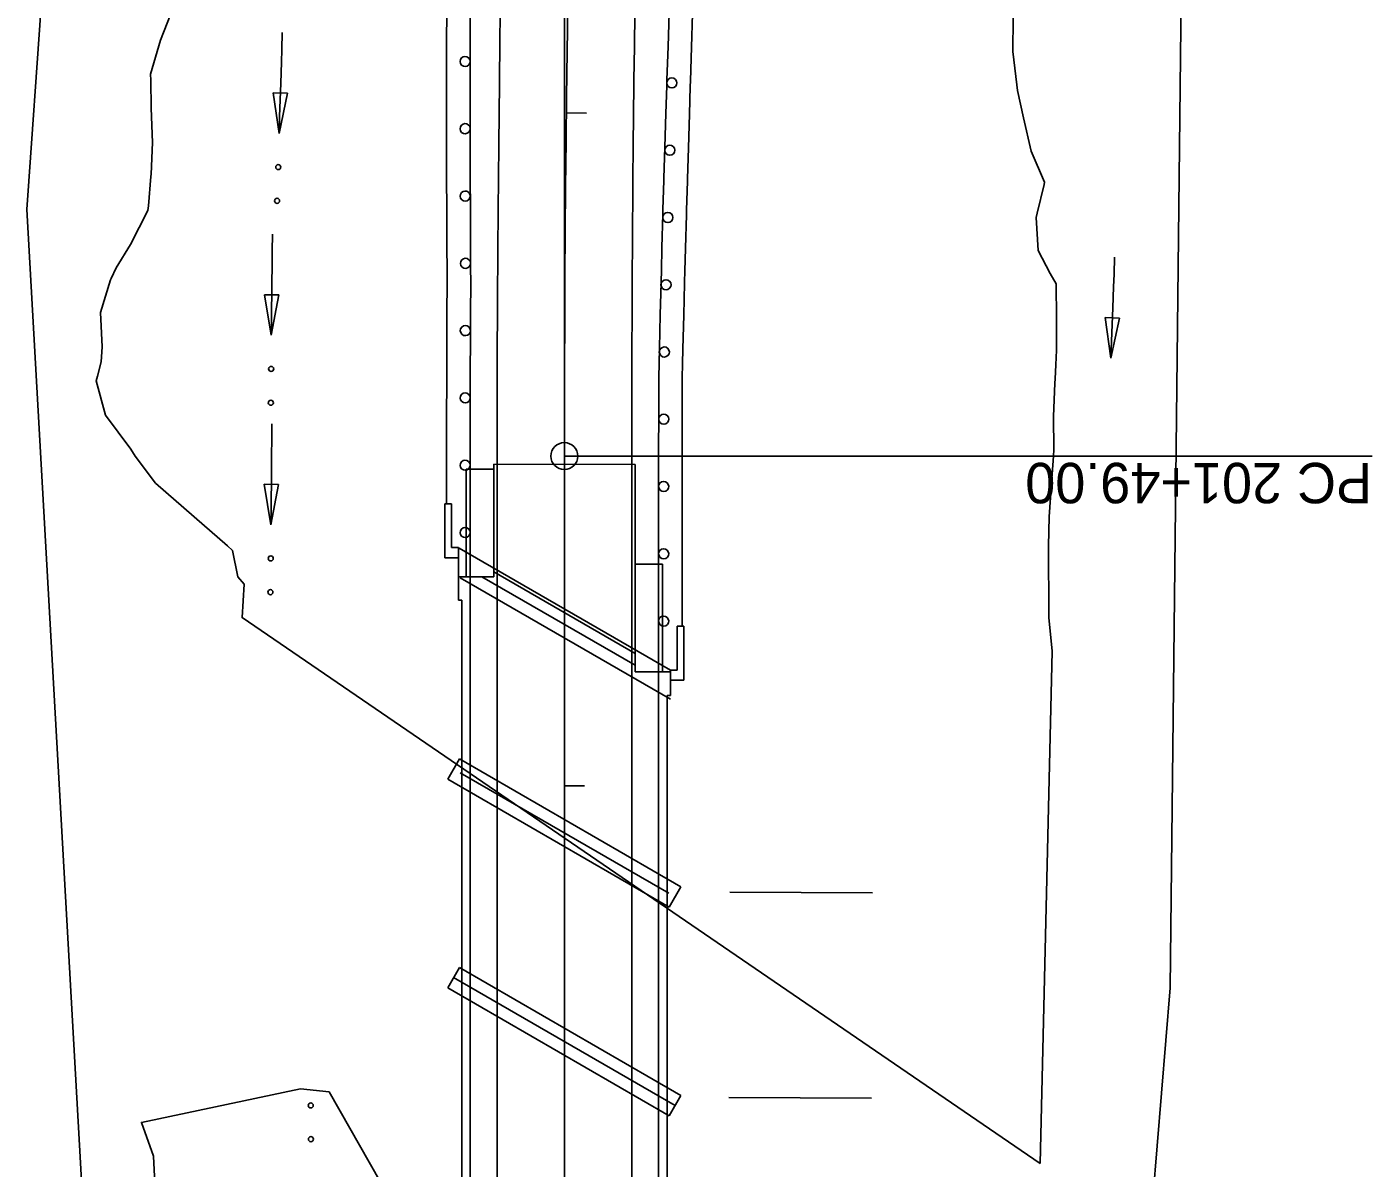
# Model space of a CAD drawing. Extents: x 1 to 1477871, y 1 to 1872901.
# Drawn here: x 1438531.3 to 1438731.2, y 1869979.6 to 1870149.1 of the extents above; entities that cross this region are included whole.
import ezdxf

# ---------------------------------------------------------------- set-up
doc = ezdxf.new("R2010")
doc.units = 0
for name, color, linetype in [('B_Centerline', 7, 'Continuous'), ('B_Concrete', 7, 'Continuous'), ('B_Concrete hidden', 7, 'Continuous'), ('R_Concrete Hidden', 7, 'Continuous'), ('R_Horz Alg', 7, 'Continuous'), ('R_Horz Alg Annot', 7, 'Continuous'), ('R_No Plot', 7, 'Continuous'), ('R_Proposed Const Limits_Cut', 7, 'Continuous'), ('R_Proposed Road_Lane', 7, 'Continuous'), ('R_Proposed Road_Shoulder', 7, 'Continuous'), ('R_ROW', 7, 'Continuous'), ('R_Steel', 7, 'Continuous'), ('R_Water', 7, 'Continuous')]:
    doc.layers.add(name, color=color, linetype=linetype)

msp = doc.modelspace()

# ---------------------------------------------------------------- linework, layer by layer
at = {"layer": 'B_Centerline'}
for p, q in [((1438626.69, 1870020.4), (1438595.69, 1870038.3)), ((1438627.64, 1869988.86), (1438594.73, 1870007.86))]:
    msp.add_line(p, q, dxfattribs=at)
at = {"layer": 'B_Concrete'}
for p, q in [((1438600.69, 1870067.43), (1438600.69, 1870084.15)), ((1438621.7, 1870084.13), (1438600.69, 1870084.15)), ((1438596.61, 1870080.35), (1438596.61, 1870083.43)), ((1438600.69, 1870083.43), (1438596.61, 1870083.43)), ((1438596.61, 1870067.43), (1438596.61, 1870080.35)), ((1438621.69, 1870080.35), (1438621.69, 1870053.28)), ((1438593.44, 1870078.26), (1438593.44, 1870070.26)), ((1438594.44, 1870078.26), (1438593.44, 1870078.26)), ((1438594.44, 1870078.26), (1438594.44, 1870071.76)), ((1438595.44, 1870070.26), (1438593.44, 1870070.26)), ((1438595.44, 1870071.76), (1438594.44, 1870071.76)), ((1438595.44, 1870070.26), (1438595.44, 1870071.76)), ((1438595.44, 1870063.93), (1438595.44, 1870070.26)), ((1438621.69, 1870056.02), (1438600.69, 1870068.15)), ((1438621.69, 1870069.28), (1438625.78, 1870069.28)), ((1438625.78, 1870053.28), (1438625.78, 1870069.28)), ((1438597.19, 1870067.43), (1438595.44, 1870067.43)), ((1438600.69, 1870067.43), (1438596.61, 1870067.43)), ((1438597.19, 1870067.43), (1438597.19, 1869943.43)), ((1438621.69, 1870054.29), (1438598.94, 1870067.43)), ((1438595.94, 1870063.93), (1438595.44, 1870063.93)), ((1438595.94, 1870063.93), (1438595.94, 1869946.93)), ((1438627.94, 1870060.07), (1438627.94, 1870053.57)), ((1438627.94, 1870060.07), (1438628.94, 1870060.07)), ((1438628.94, 1870060.07), (1438628.94, 1870052.07)), ((1438621.69, 1870053.28), (1438625.78, 1870053.28)), ((1438625.19, 1870053.28), (1438625.19, 1869929.28)), ((1438626.94, 1870053.28), (1438625.19, 1870053.28)), ((1438626.94, 1870049.78), (1438626.94, 1870053.57)), ((1438626.94, 1870053.57), (1438627.94, 1870053.57)), ((1438626.94, 1870052.07), (1438628.94, 1870052.07)), ((1438626.94, 1870049.78), (1438626.44, 1870049.78)), ((1438626.44, 1870049.78), (1438626.44, 1869932.78))]:
    msp.add_line(p, q, dxfattribs=at)
msp.add_arc((1441885.24, 1870080.35), 3263.54, 179.93377, 180, dxfattribs=at)
at = {"layer": 'B_Concrete hidden'}
for p, q in [((1438626.94, 1870053.57), (1438595.57, 1870071.68)), ((1438626.94, 1870049.24), (1438595.69, 1870067.28)), ((1438626.94, 1870052.27), (1438626.94, 1870052.7)), ((1438628.51, 1870021.37), (1438595.61, 1870040.37)), ((1438628.51, 1869990.37), (1438595.61, 1870009.37))]:
    msp.add_line(p, q, dxfattribs=at)
at = {"layer": 'R_Concrete Hidden'}
for p, q in [((1438593.86, 1870037.34), (1438595.61, 1870040.37)), ((1438626.76, 1870018.34), (1438593.86, 1870037.34)), ((1438626.76, 1870018.34), (1438628.51, 1870021.37)), ((1438593.86, 1870006.34), (1438595.61, 1870009.37)), ((1438626.76, 1869987.34), (1438593.86, 1870006.34)), ((1438626.76, 1869987.34), (1438628.51, 1869990.37))]:
    msp.add_line(p, q, dxfattribs=at)
at = {"layer": 'R_Horz Alg'}
msp.add_line((1438611.19, 1869911.35), (1438611.19, 1870085.35), dxfattribs=at)
msp.add_arc((1443194.86, 1870085.35), 4583.66, 174.66013, 180, dxfattribs=at)
at = {"layer": 'R_Horz Alg Annot'}
msp.add_line((1438611.19, 1870085.35), (1438611.19, 1870299.1), dxfattribs=at)
for points in [[(1438614.48, 1870136.32), (1438611.48, 1870136.35)], [(1438611.19, 1870085.35), (1438731.19, 1870085.35)], [(1438614.19, 1870036.35), (1438611.19, 1870036.35)]]:
    msp.add_lwpolyline(points, dxfattribs=at)
msp.add_circle((1438611.19, 1870085.35), 2, dxfattribs=at)
at = {"layer": 'R_No Plot'}
for p, q in [((1438635.77, 1870020.55), (1438656.99, 1870020.45)), ((1438635.62, 1869990.05), (1438656.84, 1869989.95))]:
    msp.add_line(p, q, dxfattribs=at)
at = {"layer": 'R_Proposed Const Limits_Cut'}
for points in [[(1438681.9, 1869980.27), (1438563.31, 1870061.35), (1438563.63, 1870066.35), (1438562.7, 1870067.42), (1438561.86, 1870071.35), (1438561.16, 1870072.03), (1438556.18, 1870076.35), (1438550.43, 1870081.35), (1438547.41, 1870085.35), (1438546.76, 1870086.37), (1438543.03, 1870091.44), (1438541.64, 1870096.52), (1438541.85, 1870097.21), (1438542.35, 1870099.34), (1438542.51, 1870101.59), (1438542.27, 1870106.67), (1438543.77, 1870111.55), (1438543.85, 1870111.74), (1438544.6, 1870113.31), (1438546.74, 1870116.79), (1438549.32, 1870121.84), (1438549.38, 1870122.53), (1438549.77, 1870126.9), (1438549.8, 1870127.25), (1438549.98, 1870131.97), (1438549.82, 1870137.04), (1438549.73, 1870141.22), (1438549.7, 1870142.11), (1438551.17, 1870147.16), (1438553.16, 1870152.19)], [(1438681.9, 1869980.27), (1438683.65, 1870056.35), (1438683.19, 1870061.35), (1438683.15, 1870066.35), (1438683.14, 1870067.42), (1438683.11, 1870071.35), (1438683.1, 1870072.03), (1438683.24, 1870076.35), (1438683.58, 1870081.35), (1438683.85, 1870085.35), (1438683.91, 1870086.34), (1438683.84, 1870091.26), (1438684.08, 1870096.18), (1438684.11, 1870096.85), (1438684.21, 1870098.91), (1438684.31, 1870101.1), (1438684.31, 1870106.02), (1438684.25, 1870110.76), (1438684.25, 1870110.94), (1438683.37, 1870112.48), (1438681.56, 1870115.88), (1438681.26, 1870120.8), (1438681.42, 1870121.47), (1438682.45, 1870125.72), (1438682.53, 1870126.05), (1438680.54, 1870130.66), (1438679.39, 1870135.6), (1438678.51, 1870139.67), (1438678.39, 1870140.53), (1438677.81, 1870145.47), (1438677.89, 1870150.4)], [(1438550.37, 1869976.35), (1438550.17, 1869981.35), (1438548.35, 1869986.35), (1438572, 1869991.35)], [(1438654.11, 1869929.27), (1438591.42, 1869964.25), (1438576.24, 1869990.87), (1438572, 1869991.35)]]:
    msp.add_lwpolyline(points, dxfattribs=at)
at = {"layer": 'R_Proposed Road_Lane'}
for points in [[(1438601.19, 1869976.35), (1438601.19, 1869981.35), (1438601.19, 1869986.35), (1438601.19, 1869991.35), (1438601.19, 1869996.35), (1438601.19, 1870001.35), (1438601.19, 1870006.35), (1438601.19, 1870011.35), (1438601.19, 1870016.35), (1438601.19, 1870021.35), (1438601.19, 1870026.35), (1438601.19, 1870031.35), (1438601.19, 1870036.35), (1438601.19, 1870041.35), (1438601.19, 1870046.35), (1438601.19, 1870051.35), (1438601.19, 1870052.27), (1438601.19, 1870053.28), (1438601.19, 1870056.35), (1438601.19, 1870061.35), (1438601.19, 1870066.35), (1438601.19, 1870067.42), (1438601.19, 1870071.35), (1438601.19, 1870072.03), (1438601.19, 1870076.35), (1438601.19, 1870081.35), (1438601.19, 1870085.35), (1438601.19, 1870086.35), (1438601.2, 1870091.37), (1438601.21, 1870096.38), (1438601.21, 1870097.06), (1438601.21, 1870099.16), (1438601.22, 1870101.39), (1438601.24, 1870106.4), (1438601.27, 1870111.23), (1438601.27, 1870111.41), (1438601.28, 1870112.97), (1438601.3, 1870116.42), (1438601.33, 1870121.43), (1438601.34, 1870122.11), (1438601.38, 1870126.44), (1438601.38, 1870126.78), (1438601.43, 1870131.45), (1438601.48, 1870136.46), (1438601.53, 1870140.59), (1438601.54, 1870141.47), (1438601.6, 1870146.48), (1438601.67, 1870151.49)], [(1438621.19, 1869976.35), (1438621.19, 1869981.35), (1438621.19, 1869986.35), (1438621.19, 1869991.35), (1438621.19, 1869996.35), (1438621.19, 1870001.35), (1438621.19, 1870006.35), (1438621.19, 1870011.35), (1438621.19, 1870016.35), (1438621.19, 1870021.35), (1438621.19, 1870026.35), (1438621.19, 1870031.35), (1438621.19, 1870036.35), (1438621.19, 1870041.35), (1438621.19, 1870046.35), (1438621.19, 1870051.35), (1438621.19, 1870052.27), (1438621.19, 1870053.28), (1438621.19, 1870056.35), (1438621.19, 1870061.35), (1438621.19, 1870066.35), (1438621.19, 1870067.42), (1438621.19, 1870071.35), (1438621.19, 1870072.03), (1438621.19, 1870076.35), (1438621.19, 1870081.35), (1438621.19, 1870085.35), (1438621.19, 1870086.35), (1438621.2, 1870091.34), (1438621.21, 1870096.33), (1438621.21, 1870097.01), (1438621.21, 1870099.1), (1438621.22, 1870101.32), (1438621.24, 1870106.31), (1438621.27, 1870111.12), (1438621.27, 1870111.3), (1438621.28, 1870112.85), (1438621.3, 1870116.29), (1438621.33, 1870121.27), (1438621.34, 1870121.95), (1438621.38, 1870126.26), (1438621.38, 1870126.6), (1438621.42, 1870131.25), (1438621.48, 1870136.24), (1438621.52, 1870140.35), (1438621.53, 1870141.23), (1438621.6, 1870146.22), (1438621.67, 1870151.21)]]:
    msp.add_lwpolyline(points, dxfattribs=at)
at = {"layer": 'R_Proposed Road_Shoulder'}
for points in [[(1438593.69, 1870078.26), (1438593.69, 1870081.35), (1438593.69, 1870085.35), (1438593.69, 1870086.36), (1438593.7, 1870091.38), (1438593.71, 1870096.4), (1438593.71, 1870097.08), (1438593.72, 1870099.19), (1438593.72, 1870101.41), (1438593.74, 1870106.43), (1438593.77, 1870111.27), (1438593.77, 1870111.45), (1438593.76, 1870113.02), (1438593.74, 1870116.47), (1438593.72, 1870121.49), (1438593.72, 1870122.17), (1438593.7, 1870126.51), (1438593.7, 1870126.85), (1438593.7, 1870131.53), (1438593.69, 1870136.55), (1438593.69, 1870140.69), (1438593.69, 1870141.57), (1438593.7, 1870146.59), (1438593.71, 1870151.61)], [(1438628.69, 1870060.07), (1438628.69, 1870061.35), (1438628.69, 1870066.35), (1438628.69, 1870067.42), (1438628.69, 1870071.35), (1438628.69, 1870072.03), (1438628.69, 1870076.35), (1438628.69, 1870081.35), (1438628.69, 1870085.35), (1438628.69, 1870086.35), (1438628.7, 1870091.33), (1438628.71, 1870096.31), (1438628.71, 1870096.99), (1438628.76, 1870099.08), (1438628.81, 1870101.29), (1438628.93, 1870106.27), (1438629.05, 1870111.07), (1438629.05, 1870111.25), (1438629.09, 1870112.81), (1438629.19, 1870116.23), (1438629.32, 1870121.21), (1438629.34, 1870121.89), (1438629.46, 1870126.19), (1438629.47, 1870126.53), (1438629.61, 1870131.17), (1438629.76, 1870136.15), (1438629.89, 1870140.25), (1438629.92, 1870141.13), (1438630.08, 1870146.1), (1438630.25, 1870151.08)]]:
    msp.add_lwpolyline(points, dxfattribs=at)
at = {"layer": 'R_ROW'}
for p, q in [((1438531.34, 1870121.98), (1438591.99, 1870985.89)), ((1438711.98, 1870984.32), (1438701.19, 1870006.35)), ((1438587.34, 1869127.27), (1438531.34, 1870121.98)), ((1438701.19, 1870006.35), (1438676.17, 1869699.24))]:
    msp.add_line(p, q, dxfattribs=at)
at = {"layer": 'R_Steel'}
for points in [[(1438597.19, 1870067.43), (1438597.19, 1870086.35), (1438597.2, 1870091.37), (1438597.21, 1870096.39), (1438597.21, 1870097.07), (1438597.21, 1870099.18), (1438597.22, 1870101.4), (1438597.24, 1870106.42), (1438597.27, 1870111.27), (1438597.27, 1870111.47), (1438597.26, 1870113.04), (1438597.24, 1870116.49), (1438597.22, 1870121.5), (1438597.22, 1870122.18), (1438597.2, 1870126.52), (1438597.2, 1870126.86), (1438597.19, 1870131.53), (1438597.19, 1870136.55), (1438597.19, 1870140.69), (1438597.19, 1870141.57), (1438597.2, 1870146.58), (1438597.21, 1870151.6)], [(1438625.19, 1870053.28), (1438625.19, 1870086.35), (1438625.2, 1870091.33), (1438625.21, 1870096.32), (1438625.21, 1870097.03), (1438625.26, 1870099.16), (1438625.31, 1870101.37), (1438625.43, 1870106.36), (1438625.55, 1870111.16), (1438625.56, 1870111.35), (1438625.6, 1870112.9), (1438625.69, 1870116.33), (1438625.82, 1870121.31), (1438625.84, 1870121.99), (1438625.96, 1870126.29), (1438625.97, 1870126.63), (1438626.11, 1870131.27), (1438626.26, 1870136.26), (1438626.39, 1870140.36), (1438626.42, 1870141.24), (1438626.59, 1870146.22), (1438626.76, 1870151.2)]]:
    msp.add_lwpolyline(points, dxfattribs=at)
for centre, major_axis in [((1438596.44, 1870144), (-0.514, -0.546)), ((1438627.16, 1870140.8), (-0.529, -0.531)), ((1438596.44, 1870134), (-0.512, -0.548)), ((1438626.85, 1870130.8), (-0.528, -0.532)), ((1438596.46, 1870123.99), (-0.511, -0.549)), ((1438626.56, 1870120.81), (-0.527, -0.534)), ((1438596.5, 1870113.99), (-0.51, -0.55)), ((1438626.29, 1870110.81), (-0.526, -0.535)), ((1438596.48, 1870104), (-0.515, -0.545)), ((1438626.04, 1870100.82), (-0.525, -0.536)), ((1438596.45, 1870094), (-0.514, -0.546)), ((1438625.95, 1870090.84), (-0.513, -0.547)), ((1438596.44, 1870084), (-0.513, -0.547)), ((1438625.94, 1870080.84), (-0.512, -0.548)), ((1438596.44, 1870074), (-0.512, -0.548)), ((1438625.94, 1870070.84), (-0.512, -0.548)), ((1438625.94, 1870060.84), (-0.512, -0.548))]:
    msp.add_ellipse(centre, major_axis=major_axis, ratio=0.998743, dxfattribs=at)
at = {"layer": 'R_Water'}
for p, q in [((1438570.06, 1870139.26), (1438567.94, 1870139.32)), ((1438567.94, 1870139.32), (1438568.81, 1870133.29)), ((1438568.81, 1870133.29), (1438570.06, 1870139.26)), ((1438568.77, 1870109.3), (1438566.66, 1870109.32)), ((1438566.66, 1870109.32), (1438567.65, 1870103.31)), ((1438567.65, 1870103.31), (1438568.77, 1870109.3)), ((1438693.67, 1870105.85), (1438691.56, 1870105.93)), ((1438691.56, 1870105.93), (1438692.39, 1870099.9)), ((1438692.39, 1870099.9), (1438693.67, 1870105.85)), ((1438568.72, 1870081.14), (1438566.6, 1870081.17)), ((1438566.6, 1870081.17), (1438567.59, 1870075.15)), ((1438567.59, 1870075.15), (1438568.72, 1870081.14))]:
    msp.add_line(p, q, dxfattribs=at)
for points in [[(1438569.28, 1870148.28), (1438569.2, 1870145.77), (1438569.14, 1870143.89), (1438569.05, 1870140.79), (1438568.89, 1870135.81), (1438568.81, 1870133.29)], [(1438567.81, 1870118.31), (1438567.78, 1870115.79), (1438567.76, 1870113.9), (1438567.73, 1870110.8), (1438567.68, 1870105.82), (1438567.65, 1870103.31)], [(1438692.94, 1870114.89), (1438692.85, 1870112.37), (1438692.78, 1870110.49), (1438692.67, 1870107.39), (1438692.49, 1870102.41), (1438692.39, 1870099.9)], [(1438567.75, 1870090.15), (1438567.72, 1870087.64), (1438567.7, 1870085.75), (1438567.67, 1870082.65), (1438567.62, 1870077.67), (1438567.59, 1870075.15)]]:
    msp.add_lwpolyline(points, dxfattribs=at)
for centre in [(1438568.68, 1870128.29), (1438568.51, 1870123.28), (1438567.63, 1870098.3), (1438567.58, 1870093.29), (1438567.57, 1870070.15), (1438567.52, 1870065.14), (1438573.5, 1869988.87), (1438573.54, 1869983.86)]:
    msp.add_circle(centre, 0.375, dxfattribs=at)

# ---------------------------------------------------------------- texts
at = {"layer": 'R_Horz Alg Annot'}
msp.add_text('PC 201+49.00', height=6, rotation=180, dxfattribs=at).set_placement((1438731.19, 1870084.35))

doc.saveas('drawing.dxf')
